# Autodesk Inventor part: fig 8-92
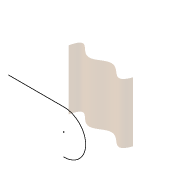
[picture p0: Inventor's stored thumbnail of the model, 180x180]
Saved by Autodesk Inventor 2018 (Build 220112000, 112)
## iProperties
Shininess: 64.0
Length Units: 11269
Angle Units: 11279
Time Units: 11290
Mass Units: 11283
Length Display Precision: 3
Angle Display Precision: 2
Compacted: True
Part Number: fig 8-92
Document SubType Name: Modeling
Created: 2003-08
Designer: Owner
Manufacturer: Standard
Standards Organization: Custom
Density: 1 g/cm^3
Material: Generic
Appearance: Default
Density: 0.0
Volumn: 0.0
Area: 0.0
PropertySet Name: Model Information
Control State: 0
Master: False
Checked Out: False
Author: Owner
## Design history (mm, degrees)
sketch "Sketch1"
  geometry: 7 further points
  constraints: 7 other
  dimensions: "d0" = 80 horizontal distance of point (40, 1.742) point (-40, -4.065); "d1" = 40 horizontal distance of point (0, 0) point (-40, -4.065)
extrude_surface "ExtrusionSrf1" sketch "Sketch1" dims "d2" = 80, "d3" = 0
sketch "Sketch2"
  geometry: L1 (40, 0)-(40, -40) reference; L2 (-40, 0)-(-40, -40) reference; 7 further points
  constraints: 2 point on line, 7 other
extrude_surface "ExtrusionSrf2" sketch "Sketch2" dims "d4" = 80, "d5" = 0
workplane "Work Plane1"
sketch "Sketch4"
  geometry: L1 (70.027, 16.004)-(-4, 16.004); A1 r 29.004 centre (-4, -13) between (-4, 16.004) and (-2.981, -41.986)
  constraints: 2 end point, 2 point on circle, 1 centre point, 1 horizontal, 1 tangent
body "Srf1"
body "Srf2"
other parameters: "d6" = -54.75
